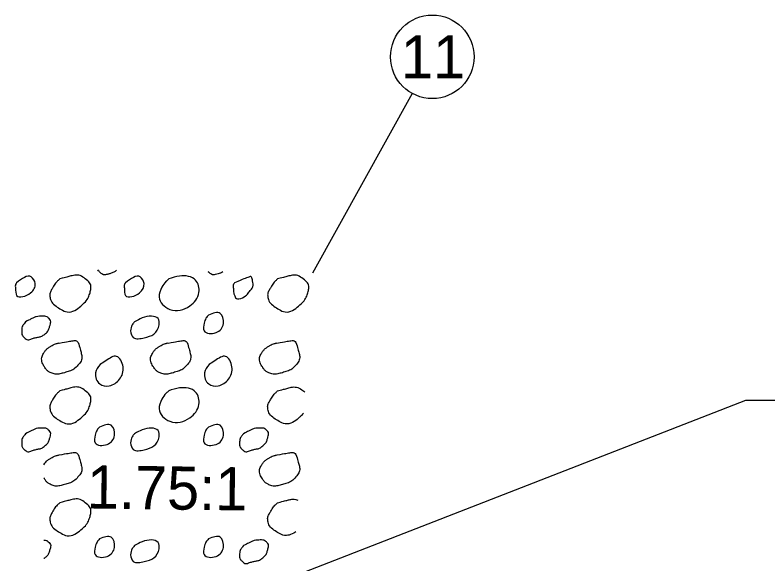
# Model space of a CAD drawing. Extents: x -1270 to 3371, y -118 to 220.
# Drawn here: x 148.55 to 172.98, y 162.09 to 179.89 of the extents above; entities that cross this region are included whole.
import ezdxf

# ---------------------------------------------------------------- set-up
doc = ezdxf.new("R2010")
doc.units = 0
for name, color, linetype in [('GE_P_Alignment', 7, 'Continuous'), ('GE_P_Alignment_100_Bearings', 7, 'Continuous'), ('TX_P_1', 7, 'Continuous')]:
    doc.layers.add(name, color=color, linetype=linetype)

msp = doc.modelspace()

# ---------------------------------------------------------------- linework, layer by layer
at = {"layer": 'GE_P_Alignment'}
msp.add_line((161.432, 177.354), (158.198, 171.516), dxfattribs=at)
at = {"layer": 'GE_P_Alignment_100_Bearings'}
for points in [[(151.842, 171.616), (151.768, 171.557), (151.689, 171.523), (151.606, 171.498), (151.51, 171.469), (151.389, 171.464), (151.295, 171.557), (151.273, 171.579), (151.253, 171.602), (151.237, 171.625)], [(155.296, 171.561), (155.247, 171.534), (155.195, 171.514), (155.142, 171.498), (155.046, 171.469), (154.925, 171.464), (154.831, 171.557), (154.827, 171.561), (154.823, 171.565), (154.819, 171.569)], [(149.997, 171.334), (150.115, 171.365), (150.234, 171.396), (150.353, 171.427), (150.526, 171.472), (150.7, 171.44), (150.874, 171.295), (151.008, 171.183), (151.017, 171.017), (150.981, 170.893), (150.936, 170.736), (150.837, 170.588), (150.685, 170.458), (150.495, 170.296), (150.231, 170.232), (150.037, 170.347), (149.879, 170.44), (149.713, 170.58), (149.683, 170.745), (149.664, 170.848), (149.717, 170.968), (149.778, 171.064), (149.821, 171.132), (149.859, 171.201), (149.916, 171.256), (149.943, 171.282), (149.97, 171.308), (149.997, 171.334)], [(155.669, 171.208), (155.828, 171.272), (155.986, 171.34), (156.144, 171.4), (156.222, 171.43), (156.263, 171.256), (156.27, 171.182), (156.28, 171.082), (156.203, 170.978), (156.121, 170.88), (156.01, 170.745), (155.729, 170.648), (155.671, 170.795), (155.64, 170.874), (155.635, 170.954), (155.632, 171.035), (155.63, 171.076), (155.615, 171.12), (155.636, 171.156), (155.647, 171.174), (155.659, 171.191), (155.669, 171.208)], [(157.069, 171.334), (157.187, 171.365), (157.306, 171.396), (157.424, 171.427), (157.598, 171.472), (157.772, 171.44), (157.945, 171.295), (158.08, 171.183), (158.088, 171.017), (158.053, 170.893), (158.008, 170.736), (157.909, 170.588), (157.757, 170.458), (157.567, 170.296), (157.303, 170.232), (157.109, 170.347), (156.951, 170.44), (156.785, 170.58), (156.754, 170.745), (156.735, 170.848), (156.789, 170.968), (156.849, 171.064), (156.893, 171.132), (156.931, 171.201), (156.988, 171.256), (157.015, 171.282), (157.042, 171.308), (157.069, 171.334)], [(148.889, 169.944), (148.973, 169.986), (149.056, 170.027), (149.139, 170.069), (149.231, 170.115), (149.341, 170.124), (149.44, 170.127), (149.514, 170.129), (149.585, 170.111), (149.651, 170.046), (149.712, 169.986), (149.703, 169.906), (149.685, 169.842), (149.656, 169.737), (149.617, 169.631), (149.514, 169.546), (149.414, 169.463), (149.309, 169.451), (149.201, 169.426), (149.088, 169.399), (148.96, 169.333), (148.849, 169.432), (148.777, 169.497), (148.762, 169.573), (148.764, 169.647), (148.765, 169.714), (148.774, 169.792), (148.815, 169.847), (148.84, 169.88), (148.865, 169.912), (148.889, 169.944)], [(149.976, 169.255), (150.127, 169.281), (150.279, 169.31), (150.43, 169.331), (150.581, 169.352), (150.652, 169.093), (150.689, 168.951), (150.724, 168.822), (150.702, 168.664), (150.593, 168.544), (150.46, 168.397), (150.311, 168.34), (150.147, 168.292), (150.006, 168.25), (149.848, 168.235), (149.707, 168.294), (149.622, 168.33), (149.56, 168.392), (149.508, 168.472), (149.421, 168.606), (149.396, 168.791), (149.471, 168.917), (149.521, 169.001), (149.589, 169.075), (149.676, 169.131), (149.75, 169.178), (149.82, 169.222), (149.902, 169.239), (149.929, 169.245), (149.957, 169.251), (149.984, 169.257)], [(153.512, 169.255), (153.663, 169.281), (153.815, 169.31), (153.966, 169.331), (154.117, 169.352), (154.187, 169.093), (154.225, 168.951), (154.26, 168.822), (154.237, 168.664), (154.129, 168.544), (153.995, 168.397), (153.847, 168.34), (153.683, 168.292), (153.542, 168.25), (153.383, 168.235), (153.243, 168.294), (153.157, 168.33), (153.095, 168.392), (153.044, 168.472), (152.957, 168.606), (152.931, 168.791), (153.007, 168.917), (153.057, 169.001), (153.125, 169.075), (153.212, 169.131), (153.286, 169.178), (153.356, 169.222), (153.438, 169.239), (153.465, 169.245), (153.493, 169.251), (153.52, 169.257)], [(157.048, 169.255), (157.199, 169.281), (157.351, 169.31), (157.502, 169.331), (157.653, 169.352), (157.723, 169.093), (157.761, 168.951), (157.796, 168.822), (157.773, 168.664), (157.664, 168.544), (157.531, 168.397), (157.383, 168.34), (157.219, 168.292), (157.077, 168.25), (156.919, 168.235), (156.779, 168.294), (156.693, 168.33), (156.631, 168.392), (156.579, 168.472), (156.493, 168.606), (156.467, 168.791), (156.543, 168.917), (156.593, 169.001), (156.661, 169.075), (156.748, 169.131), (156.821, 169.178), (156.892, 169.222), (156.974, 169.239), (157.001, 169.245), (157.029, 169.251), (157.056, 169.257)], [(149.997, 167.703), (150.115, 167.735), (150.234, 167.766), (150.353, 167.797), (150.526, 167.841), (150.7, 167.81), (150.874, 167.665), (151.008, 167.553), (151.017, 167.386), (150.981, 167.262), (150.936, 167.106), (150.837, 166.957), (150.685, 166.827), (150.495, 166.665), (150.231, 166.601), (150.037, 166.717), (149.879, 166.81), (149.713, 166.95), (149.683, 167.115), (149.664, 167.218), (149.717, 167.337), (149.778, 167.433), (149.821, 167.502), (149.859, 167.571), (149.916, 167.626), (149.943, 167.652), (149.97, 167.678), (149.997, 167.703)], [(157.906, 166.981), (157.864, 166.928), (157.814, 166.876), (157.757, 166.827), (157.567, 166.665), (157.303, 166.601), (157.109, 166.717), (156.951, 166.81), (156.785, 166.95), (156.754, 167.115), (156.735, 167.218), (156.789, 167.337), (156.849, 167.433), (156.893, 167.502), (156.931, 167.571), (156.988, 167.626), (157.015, 167.652), (157.042, 167.678), (157.069, 167.703)], [(157.069, 167.703), (157.187, 167.735), (157.306, 167.766), (157.424, 167.797), (157.598, 167.841), (157.772, 167.81), (157.945, 167.665), (157.947, 167.664), (157.948, 167.662), (157.95, 167.661)], [(148.889, 166.314), (148.973, 166.355), (149.056, 166.397), (149.139, 166.439), (149.231, 166.484), (149.341, 166.493), (149.44, 166.496), (149.514, 166.498), (149.585, 166.481), (149.651, 166.415), (149.712, 166.355), (149.703, 166.275), (149.685, 166.212), (149.656, 166.107), (149.617, 166), (149.514, 165.915), (149.414, 165.832), (149.309, 165.82), (149.201, 165.795), (149.088, 165.769), (148.96, 165.702), (148.849, 165.801), (148.777, 165.866), (148.762, 165.942), (148.764, 166.017), (148.765, 166.083), (148.774, 166.162), (148.815, 166.217), (148.84, 166.25), (148.865, 166.281), (148.889, 166.314)], [(155.961, 166.314), (156.044, 166.355), (156.128, 166.397), (156.211, 166.439), (156.303, 166.484), (156.412, 166.493), (156.512, 166.496), (156.585, 166.498), (156.656, 166.481), (156.723, 166.415), (156.783, 166.355), (156.775, 166.275), (156.757, 166.212), (156.727, 166.107), (156.688, 166), (156.586, 165.915), (156.486, 165.832), (156.38, 165.82), (156.273, 165.795), (156.16, 165.769), (156.031, 165.702), (155.921, 165.801), (155.848, 165.866), (155.833, 165.942), (155.835, 166.017), (155.837, 166.083), (155.845, 166.162), (155.887, 166.217), (155.912, 166.25), (155.936, 166.281), (155.961, 166.314)], [(149.976, 165.624), (150.127, 165.65), (150.279, 165.679), (150.43, 165.7), (150.581, 165.721), (150.652, 165.462), (150.689, 165.32), (150.724, 165.191), (150.702, 165.034), (150.593, 164.914), (150.46, 164.766), (150.311, 164.709), (150.147, 164.661), (150.006, 164.62), (149.848, 164.604), (149.707, 164.664), (149.622, 164.7), (149.56, 164.762), (149.508, 164.842), (149.499, 164.856), (149.491, 164.87), (149.483, 164.884)], [(157.048, 165.624), (157.199, 165.65), (157.351, 165.679), (157.502, 165.7), (157.653, 165.721), (157.723, 165.462), (157.761, 165.32), (157.796, 165.191), (157.773, 165.034), (157.664, 164.914), (157.531, 164.766), (157.383, 164.709), (157.219, 164.661), (157.077, 164.62), (156.919, 164.604), (156.779, 164.664), (156.693, 164.7), (156.631, 164.762), (156.579, 164.842), (156.493, 164.976), (156.467, 165.16), (156.543, 165.287), (156.593, 165.371), (156.661, 165.445), (156.748, 165.5), (156.821, 165.547), (156.892, 165.591), (156.974, 165.609), (157.001, 165.614), (157.029, 165.62), (157.056, 165.626)], [(149.483, 165.306), (149.532, 165.382), (149.596, 165.449), (149.676, 165.5), (149.75, 165.547), (149.82, 165.591), (149.902, 165.609), (149.929, 165.614), (149.957, 165.62), (149.984, 165.626)], [(149.997, 164.073), (150.115, 164.104), (150.234, 164.135), (150.353, 164.166), (150.526, 164.211), (150.7, 164.179), (150.874, 164.034), (151.008, 163.922), (151.017, 163.756), (150.981, 163.632), (150.936, 163.475), (150.837, 163.327), (150.685, 163.197), (150.495, 163.035), (150.231, 162.971), (150.037, 163.086), (149.879, 163.179), (149.713, 163.319), (149.683, 163.484), (149.664, 163.587), (149.717, 163.707), (149.778, 163.803), (149.821, 163.871), (149.859, 163.94), (149.916, 163.995), (149.943, 164.021), (149.97, 164.047), (149.997, 164.073)], [(157.658, 163.125), (157.482, 163.019), (157.271, 162.99), (157.109, 163.086), (156.951, 163.179), (156.785, 163.319), (156.754, 163.484), (156.735, 163.587), (156.789, 163.707), (156.849, 163.803), (156.893, 163.871), (156.931, 163.94), (156.988, 163.995), (157.015, 164.021), (157.042, 164.047), (157.069, 164.073)], [(157.069, 164.073), (157.187, 164.104), (157.306, 164.135), (157.424, 164.166), (157.524, 164.192), (157.625, 164.192), (157.725, 164.16)], [(149.483, 162.864), (149.542, 162.859), (149.598, 162.838), (149.651, 162.785), (149.712, 162.725), (149.703, 162.645), (149.685, 162.581), (149.656, 162.476), (149.617, 162.37), (149.514, 162.285), (149.504, 162.276), (149.494, 162.268), (149.483, 162.261)], [(155.961, 162.683), (156.044, 162.725), (156.128, 162.767), (156.211, 162.808), (156.303, 162.854), (156.412, 162.863), (156.512, 162.866), (156.585, 162.868), (156.656, 162.85), (156.723, 162.785), (156.783, 162.725), (156.775, 162.645), (156.757, 162.581), (156.727, 162.476), (156.688, 162.37), (156.586, 162.285), (156.486, 162.202), (156.38, 162.19), (156.273, 162.165), (156.16, 162.139), (156.031, 162.072), (155.921, 162.171), (155.848, 162.236), (155.833, 162.312), (155.835, 162.386), (155.837, 162.453), (155.845, 162.531), (155.887, 162.586), (155.912, 162.619), (155.936, 162.651), (155.961, 162.683)]]:
    msp.add_open_spline(points, degree=3, dxfattribs=at)
for points in [[(148.598, 171.208), (149.073, 171.4), (149.199, 171.182), (149.049, 170.88), (148.599, 170.795), (148.56, 171.035), (148.564, 171.156), (148.598, 171.208)], [(152.134, 171.208), (152.609, 171.4), (152.734, 171.182), (152.585, 170.88), (152.135, 170.795), (152.096, 171.035), (152.1, 171.156), (152.134, 171.208)], [(153.533, 171.334), (153.889, 171.427), (154.409, 171.295), (154.517, 170.893), (154.221, 170.458), (153.573, 170.347), (153.219, 170.745), (153.314, 171.064), (153.452, 171.256), (153.533, 171.334)], [(152.425, 169.944), (152.675, 170.069), (152.976, 170.127), (153.187, 170.046), (153.221, 169.842), (153.05, 169.546), (152.737, 169.426), (152.385, 169.432), (152.299, 169.647), (152.351, 169.847), (152.425, 169.944)], [(154.824, 170.161), (155.205, 170.217), (155.309, 169.888), (155.069, 169.594), (154.683, 169.651), (154.685, 169.897), (154.744, 170.06), (154.824, 170.161)], [(151.492, 168.672), (151.844, 168.823), (152.051, 168.485), (151.939, 168.08), (151.606, 167.867), (151.295, 167.927), (151.162, 168.286), (151.308, 168.553), (151.492, 168.672)], [(155.028, 168.672), (155.379, 168.823), (155.587, 168.485), (155.475, 168.08), (155.142, 167.867), (154.831, 167.927), (154.698, 168.286), (154.844, 168.553), (155.028, 168.672)], [(153.533, 167.703), (153.889, 167.797), (154.409, 167.665), (154.517, 167.262), (154.221, 166.827), (153.573, 166.717), (153.219, 167.115), (153.314, 167.433), (153.452, 167.626), (153.533, 167.703)], [(151.288, 166.53), (151.669, 166.586), (151.774, 166.258), (151.534, 165.964), (151.147, 166.02), (151.149, 166.266), (151.208, 166.429), (151.288, 166.53)], [(152.425, 166.314), (152.675, 166.439), (152.976, 166.496), (153.187, 166.415), (153.221, 166.212), (153.05, 165.915), (152.737, 165.795), (152.385, 165.801), (152.299, 166.017), (152.351, 166.217), (152.425, 166.314)], [(154.824, 166.53), (155.205, 166.586), (155.309, 166.258), (155.069, 165.964), (154.683, 166.02), (154.685, 166.266), (154.744, 166.429), (154.824, 166.53)], [(151.288, 162.9), (151.669, 162.956), (151.774, 162.627), (151.534, 162.333), (151.147, 162.39), (151.149, 162.636), (151.208, 162.799), (151.288, 162.9)], [(154.824, 162.9), (155.205, 162.956), (155.309, 162.627), (155.069, 162.333), (154.683, 162.39), (154.685, 162.636), (154.744, 162.799), (154.824, 162.9)], [(152.425, 162.683), (152.675, 162.808), (152.976, 162.866), (153.187, 162.785), (153.221, 162.581), (153.05, 162.285), (152.737, 162.165), (152.385, 162.171), (152.299, 162.386), (152.351, 162.586), (152.425, 162.683)]]:
    msp.add_spline(points, degree=3, dxfattribs=at)
at = {"layer": 'TX_P_1'}
for p, q in [((129.983, 150.963), (172.267, 167.403)), ((172.267, 167.403), (173.831, 167.403))]:
    msp.add_line(p, q, dxfattribs=at)
msp.add_circle((162.089, 178.539), 1.355, dxfattribs=at)

# ---------------------------------------------------------------- texts
at = {"layer": 'GE_P_Alignment'}
msp.add_text('1.75:1', height=1.4, rotation=359.25, dxfattribs=at).set_placement((150.871, 163.89))
at = {"layer": 'TX_P_1'}
msp.add_text('11', height=1.4, dxfattribs=at).set_placement((161.072, 177.839))

doc.saveas('drawing.dxf')
